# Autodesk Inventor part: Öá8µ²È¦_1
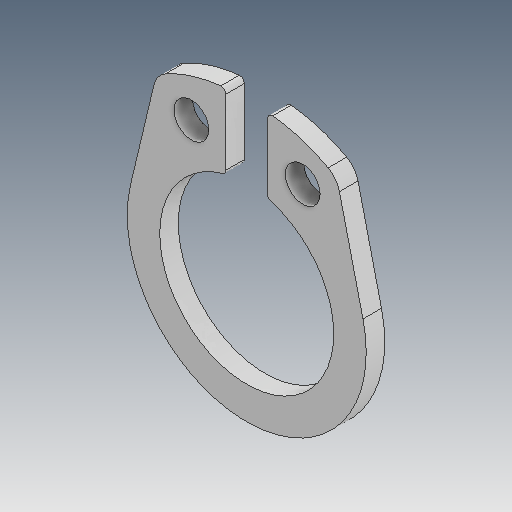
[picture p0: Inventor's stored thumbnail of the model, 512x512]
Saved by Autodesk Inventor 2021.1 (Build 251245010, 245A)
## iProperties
Created: 2019-04
Part Number: Öá8µ²È¦_1
Material: Ogólny
Document SubType Name: Modeling
Designer: user
Density: 1 g/cm^3
Appearance: Domyślna
Author: user
Revision Number: ÈÎºÎ
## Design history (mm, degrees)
feature "ÊäÈë1"
node "Bryła1"
